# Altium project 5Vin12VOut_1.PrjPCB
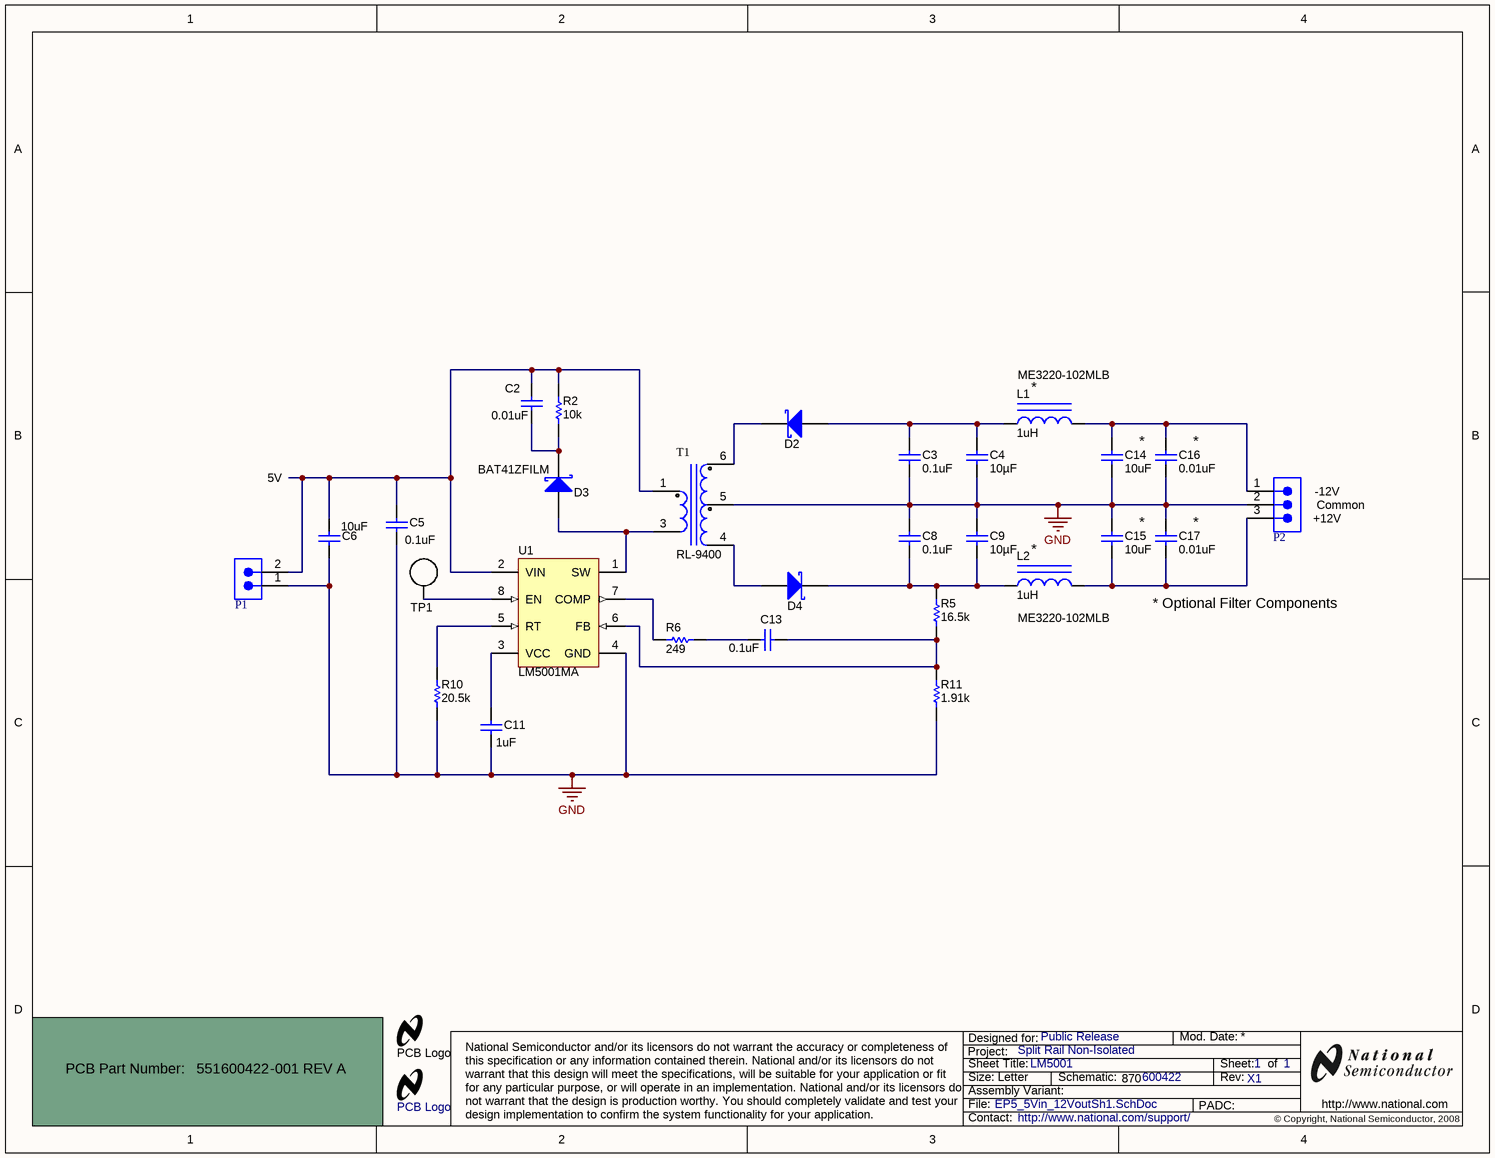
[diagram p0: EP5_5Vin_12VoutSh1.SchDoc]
TechSupport: http://www.national.com/support; SCH_Rev: X1; PRJ_Title: Split Rail Non-Isolated; PRJ_Customer: Public Release; PRJ_BasePN: 600422; PCB_MinorRev: -001 REV A
1 sheet, 31 parts. Net scope: global (net labels, ports and power ports of the same name join across sheets).
Board file: EP5_5Vin_12Vouts1.PcbDoc

## Sheet EP5_5Vin_12VoutSh1.SchDoc: LM5001
size Letter; Author: R. H.; Organization: National Semiconductor; Address1: 2900 Semiconductor Dr.; Address3: Santa Clara, CA  95051; Address4: United States; Revision: XP-1; SheetNumber: 1; SheetTotal: 1; TechSupport: http://www.national.com/support/; PageSetup: Record=PageOptions|CenterHorizontal=True|CenterVertical=True|PrintScale=0.94|XCorrection=1.00|YCorrection=1.00|PrintKind=0|BorderSize=5000000|LeftOffset=0|BottomOffset=0|Orientation=2|PaperLength=1000|PaperWidth=1000|Scale=100|PaperSource=7|PrintQuality=-4|MediaType=1|DitherType=10|PaperKind=Letter 8.5 x 11in|PrintScaleMode=1

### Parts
AA  Printed Circuit Board  (value not drawn)  (mechanical)
C2  value 0.01uF  [0603]  (hidden comment: C1608X7R1H103K)
C3  value 0.1uF  [0805]  (hidden comment: C0805C104J5RACTU)
C4  ValueDisplayed: 10µF  [2220]  (hidden comment: 0805YD106MAT2A)
C5  value 0.1uF  [0603]  (hidden comment: GRM188R71E104KA01D)
C6  value 10uF  [1210]  (hidden comment: C1210C106K8PACTU)
C8  value 0.1uF  [0805]  (hidden comment: C0805C104J5RACTU)
C9  ValueDisplayed: 10µF  [2220]  (hidden comment: 0805YD106MAT2A)
C11  value 1uF  [0603]  (hidden comment: GRM188R71C105KA12D)
C13  value 0.1uF  [0603]  (hidden comment: GRM188R71E104KA01D)
C14  value 10uF  [0805]  (hidden comment: EMK212BJ106KG-T)
C15  value 10uF  [0805]  (hidden comment: EMK212BJ106KG-T)
C16  value 0.01uF  [0603]  (hidden comment: C1608X7R1H103K)
C17  value 0.01uF  [0603]  (hidden comment: C1608X7R1H103K)
D2  PMEG6010CEH,115  [SOD-123]  (value not drawn)
D3  BAT41ZFILM  [SOD-123]
D4  PMEG6010CEH,115  [SOD-123]  (value not drawn)
L1  value 1uH  [ME3220]  (hidden comment: ME3220-102MLB)
L2  value 1uH  [ME3220]  (hidden comment: ME3220-102MLB)
Logo1  PCB Logo  [Logo_SolderMask_Small]  (no BOM)
Logo2  PCB Logo  [Worldmark_CopperSolderMask_Small]  (no BOM)
P1  TSW-102-07-T-S  [TSW-102-07-X-S]  (value not drawn)
P2  TSW-103-07-T-S  [TSW-103-07-X-S]  (value not drawn)
R2  value 10k  [0603]  (hidden comment: CRCW060310k0JNEA)
R5  value 16.5k  [0603]  (hidden comment: CRCW060316k5FKEA)
R6  value 249  [0603]  (hidden comment: CRCW0603249RFKEA)
R10  value 20.5k  [0603]  (hidden comment: CRCW060320k5FKEA)
R11  value 1.91k  [0603]  (hidden comment: CRCW06031K91FKEA)
T1  RL-9400  [S32890]
TP1  TESTPOINT  [TESTPOINT]  (value not drawn)  (no BOM)
U1  LM5001MA  [M08A_N]

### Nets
GND: C3.2 C4.1 C5.2 C6.2 C8.1 C9.2 C11.2 C14.2 C15.1 C16.2 C17.1 P1.1 P2.2 R10.1 R11.2 T1.5 U1.4(GND)
NetC2_1: C2.1 C5.1 C6.1 P1.2 R2.1 T1.1 U1.2(VIN)
NetC2_2: C2.2 D3.2(K) R2.2
NetC3_1: C3.1 C4.2 D2.1(A) L1.1
NetC8_2: C8.2 C9.1 D4.2(K) L2.1 R5.1
NetC11_1: C11.1 U1.3(VCC)
NetC13_1: C13.1 R6.2
NetC13_2: C13.2 R5.2 R11.1 U1.6(FB)
NetC14_1: C14.1 C16.1 L1.2 P2.1
NetC15_2: C15.2 C17.2 L2.2 P2.3
NetD2_2: D2.2(K) T1.6
NetD3_1: D3.1(A) T1.3 U1.1(SW)
NetD4_1: D4.1(A) T1.4
NetR6_1: R6.1 U1.7(COMP)
NetR10_2: R10.2 U1.5(RT)
NetTP1_1: TP1.1 U1.8(EN)

Not connected (* = marked no-connect by the designer): T1 2

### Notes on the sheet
- (near L1) *
- 5V
- *
- (near C16) *
- (near P2) -12V
- (near P2) Common
- (near L2) *
- (near C17) *
- (near P2) +12V
- * Optional Filter Components

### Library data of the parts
AA = PCB: Manufacturer: TBD; SymbolCreator: codlsc
C2 = C1608X7R1H103K: Ceramic, X7R, 50V, 10%; Manufacturer: TDK; CompType: Capacitor; Value1: 0.0539 Ohm; Polarized: N; Cap_F: 10.0E-9; ESR_Ohm: 0.0539; TaMax_C: 125; TaMin_C: -55; Tolerance_%: 10; VDC_V: 50
C3 C8 = C0805C104J5RACTU: Ceramic, X7R, 50V, 5%; Manufacturer: Kemet; CompType: Capacitor; Polarized: N; Cap_F: 100.0E-9; ESR_Ohm: 0.064; IRMS_A: 1.64; TaMax_C: 125; TaMin_C: -55; Tolerance_%: 5; Value1: 0.064Ohm; VDC_V: 50
C4 C9 = 0805YD106MAT2A: CAP, CERM, 10uF, 16V, +/-20%, X5R, 0805; Manufacturer: AVX; Cap_Case: 0805; CompType: Capacitor; Polarized: N; TaMax_C: 85; TaMin_C: -55; Tolerance_%: 20; VDC_V: 16; Cap_F: 10.0E-6
C5 = GRM188R71E104KA01D: Ceramic, X7R, 25V, 10%; Manufacturer: MuRata; CompType: Capacitor; Polarized: N; Cap_F: 100.0E-9; TaMax_C: 125; TaMin_C: -55; Tolerance_%: 10; VDC_V: 25
C6 = C1210C106K8PACTU: Ceramic, X5R, 10V, 10%; Manufacturer: Kemet; CompType: Capacitor; Value1: 0.008 Ohm; Polarized: N; Cap_F: 10.0E-6; ESR_Ohm: 0.008; IRMS_A: 6.9; TaMax_C: 85; TaMin_C: -55; Tolerance_%: 10
C11 = GRM188R71C105KA12D: Ceramic, X7R, 16V, 10%; Manufacturer: MuRata; CompType: Capacitor; Polarized: N; ESR_Ohm: 0.011; TaMax_C: 125; TaMin_C: -55; Tolerance_%: 10; VDC_V: 16; Cap_F: 1.0E-6; Value1: 0.011 Ohm
C13 = GRM188R71E104KA01D: Ceramic, X7R, 25V, 10%; Manufacturer: MuRata; Polarized: N; CompType: Capacitor; Cap_F: 100.0E-9; TaMax_C: 125; TaMin_C: -55; Tolerance_%: 10; VDC_V: 25
C14 C15 = EMK212BJ106KG-T: Ceramic, X5R, 16V, 10%; Manufacturer: Taiyo Yuden; Polarized: N; CompType: Capacitor; Value1: Ohm; Cap_F: 10.0E-6; TaMax_C: 85; TaMin_C: -55; Tolerance_%: 10; VDC_V: 16
C16 C17 = C1608X7R1H103K: Ceramic, X7R, 50V, 10%; Manufacturer: TDK; Polarized: N; CompType: Capacitor; Value1: 0.0539Ohm; Cap_F: 10.0E-9; ESR_Ohm: 0.0539; TaMax_C: 125; TaMin_C: -55; Tolerance_%: 10; VDC_V: 50
D2 D4 = PMEG6010CEH,115: Diode, Schottky, 60V, 1A, SOD-123F; Manufacturer: NXP Semiconductor; Value: 0.57V; Vf_V: 0.57; Io_A: 1; Vr_V: 60; TJMax_C: 150
D3 = BAT41ZFILM: Vr = 100V, Io = 0.2A, Vf = 1V; Manufacturer: ST Microelectronics; CompType: Diode; Type: Schottky; Vf_V: 1; Io_A: 0.2; Vr_V: 100; TJMax_C: 150
L1 L2 = ME3220-102MLB: Drum Core, 2.6A, 0.058 Ohm; Manufacturer: Coilcraft Inc.; CompType: Inductor; Material: Ferrite; DCR_Ohm: 0.058; Imax_A: 2.6; Ind_H: 1.0E-6
Logo1 Logo2 = NSC Logo: National Semiconductor logo or worldmark; SymbolCreator: codlsc
P1 = TSW-102-07-T-S: Header, TH, 100mil, 1x2, Tin plated, 230 mil above insulator; Manufacturer: Samtec Inc.
P2 = TSW-103-07-T-S: Header, TH, 100mil, 1x3, Tin plated, 230 mil above insulator; Manufacturer: Samtec Inc.
R2 = CRCW060310k0JNEA: 5%, 0.1W; Manufacturer: Vishay-Dale; CompType: Resistor; Value_Code: 10k0; EIA_Code: E24; Power_W: 0.1; Res_Ohm: 10000; Tolerance_%: 5; VDC_V: 75
R5 = CRCW060316k5FKEA: 1%, 0.1W; Manufacturer: Vishay-Dale; CompType: Resistor; Tolerance_%: 1; VDC_V: 75; Power_W: 0.1; Res_Ohm: 16500; Value_Code: 16k5; EIA_Code: E96
R6 = CRCW0603249RFKEA: 1%, 0.1W; Manufacturer: Vishay-Dale; CompType: Resistor; Value_Code: 249R; EIA_Code: E96; Power_W: 0.1; Tolerance_%: 1; VDC_V: 75
R10 = CRCW060320k5FKEA: 1%, 0.1W; Manufacturer: Vishay-Dale; CompType: Resistor; Value_Code: 20k5; EIA_Code: E96; Power_W: 0.1; Res_Ohm: 20500; Tolerance_%: 1; VDC_V: 75
R11 = CRCW06031K91FKEA: RES, 1.91k ohm, 1%, 0.1W, 0603; Manufacturer: Vishay-Dale; CompType: Resistor; Tolerance_%: 1; VDC_V: 75; Power_W: 0.1; Res_Ohm: 1910; Value_Code: 1k91; EIA_Code: E96
T1 = RL-9400: Flyback Transfomer; Manufacturer: Renco Electronics, Inc.; Ns2toNp: 5:1; CompType: Transformer; LeakageL: 300nH; Lp: 20.0uH; Rp: 0.275 ohm; Rs1: 7.50; Rs2: 7.00; SymbolCreator: codlsc
TP1 = TESTPOINT: TEST POINT.  No entry in BOM.
U1 = LM5001MA: High Voltage Switch Mode Regulator; Manufacturer: National Semiconductor; CompType: Switcher; PackageTopMarking: NSZXTT*L5001*MA

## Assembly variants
-100A: all parts fitted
